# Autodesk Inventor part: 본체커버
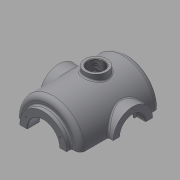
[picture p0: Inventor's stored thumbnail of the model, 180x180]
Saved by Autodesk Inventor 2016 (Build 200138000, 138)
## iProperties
Created: 2016-02
Part Number: 본체커버
Material: 일반
Document SubType Name: Modeling
Designer: mduedu
Density: 1 g/cm^3
Appearance: 기본값
Mass: 438.034 g
Surface Area: 904.884 cm^2
Volume: 438.034 cm^3
Author: mduedu
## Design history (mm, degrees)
sketch "스케치2"
  geometry: L1 (0, 90)-(0, -90); L2 (65, -65.993)-(65, 90); L3 (65, 90)-(0, 90); A1 r 100 centre (0, 10) between (0, -90) and (65, -65.993); 2 further points
  constraints: 6 end point, 2 point on circle, 1 centre point, 1 coincident, 1 horizontal, 1 midpoint, 1 parallel, 1 point on line, 1 vertical
  dimensions: "d3" = 180 distance of L1.start L1.end; "d5" = 130 diameter of L2 L1; "d6" = 100 radius of A1
revolve "회전1" sketch "스케치2" stored, may be unused: angle "d7" = 90 deg
sketch "스케치3"
  geometry: C1 r 47.5 at (0, 0); 1 further point
  constraints: 1 centre point, 1 coincident
  dimensions: "d8" = 95 diameter of C1
extrude "돌출2" join sketch "스케치3" distance "d10" = 10; taper "d11" = 0 deg
sketch "스케치5"
  geometry: L1 (47.5, 100)-(47.5, 90) reference; L2 (47.5, 90)-(65, 90) reference; L3 (65, 90)-(65, -65.993) reference; L4 (-65, -65.993)-(-65, 90) reference; L5 (-65, 90)-(-47.5, 90) reference; L6 (-47.5, 90)-(-47.5, 100) reference; L7 (-47.5, 100)-(47.5, 100) reference; L8 (55, 75)-(55, -61.239); L9 (0, 75)-(55, 75); L10 (0, 75)-(0, -80); A1 r 100 centre (0, 10) between (-65, -65.993) and (0, -90) reference; A2 r 100 centre (0, 10) between (0, -90) and (65, -65.993) reference; A3 r 90 centre (0, 10) between (0, -80) and (55, -61.239); 1 further point
  constraints: 6 end point, 2 point on circle, 1 centre point, 1 parallel, 1 perpendicular, 1 point on line, 1 vertical
  dimensions: "d13" = 10 distance between parallel lines of L3 L8; "d14" = 10 radial gap between concentric circles of A3 A1; "d15" = 15 distance between parallel lines of L9 L2
revolve "회전2" sketch "스케치5" stored, may be unused: angle "d16" = 90 deg
hole "구멍1" diameter "d19" = 65; stored, may be unused: countersink angle "d23" = 90 deg, drill point angle "d25" = 118 deg; dims "d17" = 10, "d18" = 10, "d20" = 6, "d21" = 4, "d22" = 2, "d24" = 8
node "작업 평면1"
sketch "스케치6"
  geometry: L1 (47.5, 100)-(-47.5, 100) reference; C1 r 40 at (0, -7); 1 further point
  constraints: 1 centre point, 1 vertical alignment
  dimensions: "d27" = 80 diameter of C1; "d29" = 107 distance from line of C1.centre L1
extrude "돌출3" join sketch "스케치6" stored distance "d30" = 10; taper "d31" = 0 deg
hole "구멍2" diameter "d34" = 42; stored, may be unused: countersink angle "d38" = 90 deg, drill point angle "d40" = 118 deg; dims "d32" = 10, "d33" = 10, "d35" = 6, "d36" = 52, "d37" = 18, "d39" = 8
sketch "스케치7" dims "d41" = 65
  geometry: C1 r 40 at (0, 0) reference; 3 further points
  constraints: 2 vertical alignment, 1 coincident, 2 other
hole "구멍3" sketch "스케치7" at (0, 32.5) diameter "d43" = 3.242; stored, may be unused: countersink angle "d47" = 90 deg, drill point angle "d49" = 118 deg; dims "d44" = 11, "d45" = 13, "d46" = 18, "d48" = 13
sketch "스케치8" dims "d53" = 80
  geometry: 3 further points
  constraints: 2 vertical alignment, 1 coincident, 2 other
hole "구멍4" sketch "스케치8" at (0, -40) diameter "d56" = 3.242; stored, may be unused: countersink angle "d60" = 90 deg, drill point angle "d62" = 118 deg; dims "d57" = 11, "d58" = 13, "d59" = 18, "d61" = 13
fillet "모깎기1" dims "d66" = 10
fillet "모깎기2" dims "d67" = 3
fillet "모깎기3" dims "d68" = 0.3
chamfer "모따기1" distance "d69" = 1; stored, may be unused: second distance "d70" = 2, angle "d71" = 45 deg
node "작업 평면5"
sketch "스케치10"
  geometry: L1 (-50, 66)-(50, 66); L2 (50, 66)-(50, 50); L3 (50, 50)-(-50, 50); L4 (-50, 50)-(-50, 66); 2 further points
  constraints: 8 end point, 2 horizontal, 2 vertical, 1 midpoint, 1 vertical alignment
  dimensions: "d177" = 50 distance from line of L3 point (0, 0); "d178" = 100 distance of L1.start L1.end; "d179" = 16 distance of L3.end L1.start
extrude "돌출5" join sketch "스케치10" stored distance "d84" = 10; taper "d85" = 0 deg
sketch "스케치21" dims "d180" = 220, "d182" = 130
  geometry: L1 (65, 58)-(-65, 58); L2 (-65, 58)-(-65, -32); L3 (-65, -32)-(65, -32); L4 (65, -32)-(65, 58); L5 (50, 50)-(50, 66) reference; 4 further points
  constraints: 8 end point, 3 horizontal alignment, 3 midpoint, 2 parallel, 1 horizontal, 1 perpendicular, 1 vertical alignment, 4 other
extrude "돌출13" join sketch "스케치21" distance "d183" = 10; taper "d184" = 0 deg
sketch "스케치11"
  geometry: L1 (-65, 80)-(-65, -61.239) reference; L2 (-100, -97)-(-100, -32) reference; L3 (-65, -42.793)-(-100, -63); L4 (-100, -97)-(-110, -97) reference; 1 further point
  constraints: 2 end point, 2 point on line
  dimensions: "d185" = 34 distance from line of L3.end L4; "d186" = 120 deg angle of L2 L3
feature "리브1" sketch "스케치11" dims "d88" = 1, "d89" = 16, "d90" = 0, "d91" = 0, "d92" = 1, "d93" = 1
fillet "모깎기12"
fillet "모깎기13"
fillet "모깎기16" dims "d167" = 3
fillet "모깎기18"
fillet "모깎기17" dims "d168" = 3
fillet "모깎기19" dims "d187" = 3
node "작업 평면6"
sketch "스케치19"
  geometry: L1 (75, -47)-(75, 33) reference; L2 (-75, -47)-(-75, 33) reference; L3 (75, -7)-(-75, -7); C1 r 22.5 at (0, -7); 1 further point
  constraints: 3 midpoint, 2 end point, 1 centre point
  dimensions: "d149" = 45 diameter of C1
extrude "돌출11" join sketch "스케치19" stored distance "d150" = 10; taper "d151" = 0 deg
hole "구멍6" diameter "d154" = 33.376; stored, may be unused: countersink angle "d158" = 90 deg, drill point angle "d160" = 118 deg; dims "d155" = 6, "d156" = 4, "d157" = 2, "d159" = 8, "d190" = 10, "d191" = 10
fillet "모깎기11" dims "d161" = 3
chamfer "모따기3" distance "d164" = 1; stored, may be unused: second distance "d165" = 2, angle "d166" = 45 deg
sketch "스케치22" dims "d189" = 20
  geometry: L1 (-10, -123)-(10, -123); L2 (10, -123)-(10, -103); L3 (10, -103)-(-10, -103); L4 (-10, -103)-(-10, -123); A1 r 65 centre (0, -58) between (-65, -58) and (65, -58) reference; 2 further points
  constraints: 8 end point, 2 parallel, 1 horizontal, 1 horizontal alignment, 1 midpoint, 1 perpendicular, 1 tangent, 1 vertical alignment, 2 other
  dimensions: "d193" = 30 dimension on L1
extrude "돌출14" cut sketch "스케치22" stored distance "d194" = 10; taper "d195" = 0 deg
fillet "모깎기21" dims "d196" = 3
feature "분할1"
node "솔리드2"
pattern_circular "원형 패턴1" dims angle "d51" = 360 deg
mirror "대칭1"
pattern_circular "원형 패턴2" dims angle "d64" = 360 deg
node "절단 모서리 투영1"
other parameters: "d26" = 75, "d136" = 175
